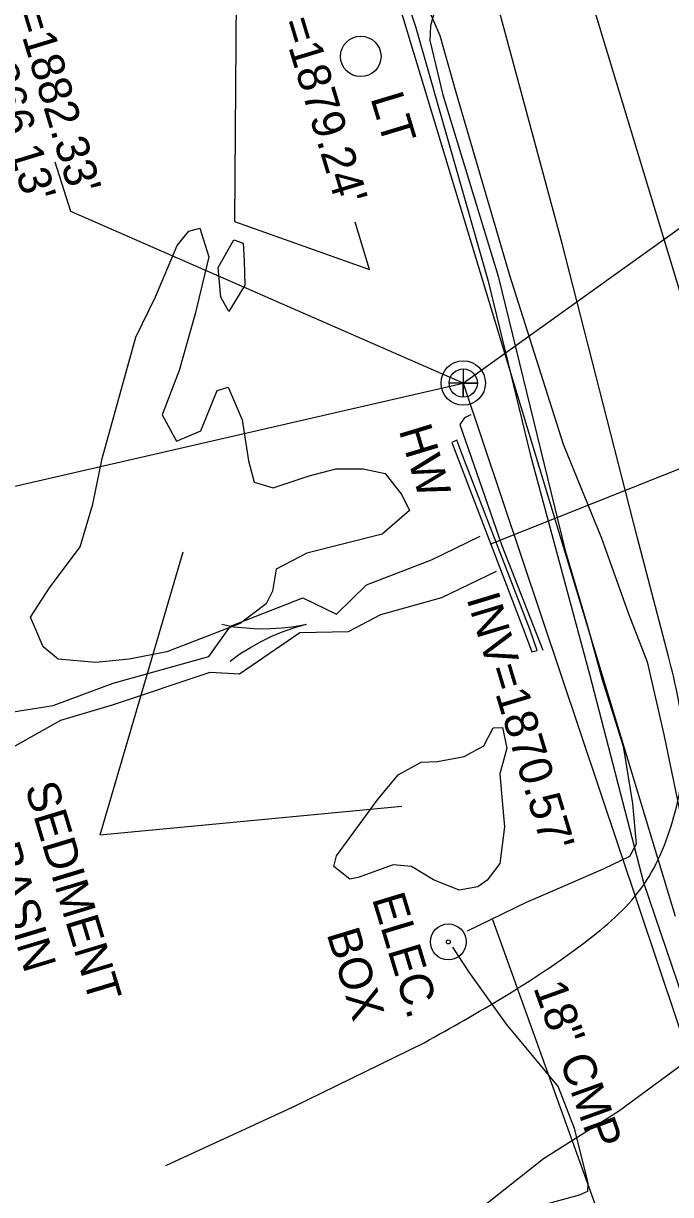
# Model space of a CAD drawing. Extents: x 553786 to 558838, y 502329 to 507342.
# Drawn here: x 555425.2 to 555503.7, y 503924.4 to 504066.5 of the extents above; entities that cross this region are included whole.
import ezdxf

# ---------------------------------------------------------------- set-up
doc = ezdxf.new("R2010")
doc.units = 0
for name, color, linetype in [('Exist Hydro Jurisdictional Stream or Body of Water', 7, 'Continuous'), ('Exist Hydro Stream Flow Arrow CELL', 7, 'Continuous'), ('Exist Hydrographic Top of Bank', 7, 'Continuous'), ('Exist Other Culture Area Outline Leader', 7, 'Continuous'), ('Exist Other Culture Area Outline Text', 7, 'Continuous'), ('Exist Structure Minor Head and End Wall Text', 7, 'Continuous'), ('Exist Structure Minor Pipes CMAP 103inx71in Invert', 7, 'Continuous'), ('Exist Structure Minor Pipes CMP 18 Inch', 7, 'Continuous'), ('Exist Structure Minor Pipes CMP 18 Inch Text', 7, 'Continuous'), ('Exist Structure Minor Pipes CMP 30 Inch', 7, 'Continuous'), ('Exist Structure Minor Pipes CMP 30 Inch Invert', 7, 'Continuous'), ('Exist Structure Minor Pipes CMP 30 Inch Leader', 7, 'Continuous'), ('Exist Utilities Other Located Object CELL', 7, 'Continuous'), ('Exist Utilities Other Located Object Text', 7, 'Continuous'), ('Exist Utilities Other Pole CELL', 7, 'Continuous'), ('Exist Utilities Other Pole Text', 7, 'Continuous'), ('Exist Utilities Sanitary Sewer Manhole Leader', 7, 'Continuous'), ('Exist Utilities Sanitary Sewer Manhole Text', 7, 'Continuous'), ('Exist Utilities Sanitary Sewer UG Line', 7, 'Continuous'), ('Exist Utilities Sanitary Sewer UG Line Invert Elevation', 7, 'Continuous'), ('Exist Vertical Profile Ground Line', 7, 'Continuous'), ('Prop Drainage Structure Catch Basin Grate 840 03F Label', 7, 'Continuous'), ('Prop Drainage Structure Pipe Alternate 24in', 7, 'Continuous'), ('Prop Drainage Structure Pipe Alternate 36in', 7, 'Continuous'), ('Prop Drainage Structure Pipe RCP 15in Class III', 7, 'Continuous'), ('Prop Drainage Structure Pipe RCP 15in Class III Label', 7, 'Continuous'), ('Prop Drainage Structure Pipe RCP 18in Class IV', 7, 'Continuous'), ('Prop Earthen Structure Tail Ditch Label', 7, 'Continuous'), ('Prop Erosion Rip Rap Pad Outlet for Jurisdictional Stream CELL', 7, 'Continuous'), ('Sheet Layout Plan Border', 7, 'Continuous')]:
    doc.layers.add(name, color=color, linetype=linetype)

# ---------------------------------------------------------------- blocks, each defined once
blk = doc.blocks.new('EXIST UTILITIES SANITARY SEWER MANHOLE')
at = {"layer": 'Prop Drainage Structure Catch Basin Grate 840 03F Label'}
blk.add_lwpolyline([(0, 0.03425), (0, -0.03425), (0, 0), (0.03425, 0), (-0.03425, 0)], dxfattribs=at)
for radius in [0.05389, 0.03425]:
    blk.add_circle((0, 0), radius, dxfattribs=at)

msp = doc.modelspace()

# ---------------------------------------------------------------- linework, layer by layer
at = {"layer": 'Exist Hydro Jurisdictional Stream or Body of Water'}
for points in [[(555450.1, 504031.56), (555449.11, 504033.28), (555448.78, 504036.89), (555450.72, 504040.25), (555451.83, 504039.85), (555451.96, 504037.68), (555452.02, 504034.76), (555450.1, 504031.56)], [(555410.59, 503980.79), (555422.92, 503982.82), (555428.76, 503983.74), (555436.04, 503986.44), (555447.65, 503989.69), (555450.28, 503993.37), (555459.09, 503996.81), (555463.15, 503994.84), (555466.8, 503998.39), (555474.67, 504001.41), (555480.6, 504004.27)], [(555411.01, 503976.66), (555422.87, 503978.1), (555429.7, 503981.94), (555435.97, 503983.8), (555447.83, 503987.78), (555451.37, 503987.58), (555458.73, 503992.59), (555464.6, 503992.73), (555468.52, 503994.78), (555475.95, 503996.86), (555482.57, 504000.03)]]:
    msp.add_lwpolyline(points, dxfattribs=at)
at = {"layer": 'Exist Hydro Stream Flow Arrow CELL'}
msp.add_line((555454.64, 503992.47), (555454.64, 503992.47), dxfattribs=at)
for points in [[(555449.25, 503993.59), (555450.69, 503993.3), (555452.18, 503993.17), (555453.66, 503993.06), (555455.1, 503993.07), (555456.58, 503993.16), (555458.07, 503993.34), (555459.51, 503993.59)], [(555450.27, 503989.13), (555451.44, 503990.01), (555452.73, 503990.78), (555454.01, 503991.52), (555455.32, 503992.14), (555456.69, 503992.7), (555458.1, 503993.19), (555459.51, 503993.59)]]:
    msp.add_lwpolyline(points, dxfattribs=at)
at = {"layer": 'Exist Hydrographic Top of Bank'}
msp.add_lwpolyline([(555454.73, 503900.13), (555461.06, 503904.46), (555466.29, 503907.66), (555471.13, 503910.31), (555473.27, 503914.4), (555479.75, 503922.01), (555488.3, 503928.78), (555497.38, 503934.53), (555512.87, 503945.92), (555521.69, 503954.59), (555530.33, 503963.4), (555533.78, 503966.67), (555538.03, 503970.02), (555540.47, 503971.18), (555541.14, 503972.36), (555541.05, 503973.88), (555540.1, 503976.62), (555537.96, 503985.99), (555539.43, 503986.04), (555541.64, 503987.48), (555544.42, 503988.72)], dxfattribs=at)
at = {"layer": 'Exist Other Culture Area Outline Leader'}
for p in [(555444.5, 504002.35), (555471.09, 503971.47)]:
    msp.add_line(p, (555434.42, 503967.99), dxfattribs=at)
at = {"layer": 'Exist Structure Minor Pipes CMP 18 Inch'}
msp.add_line((555496.09, 503918.99), (555482.14, 503957.75), dxfattribs=at)
at = {"layer": 'Exist Structure Minor Pipes CMP 30 Inch'}
msp.add_line((555451.41, 504141.86), (555450.8, 504042.46), dxfattribs=at)
at = {"layer": 'Exist Structure Minor Pipes CMP 30 Inch Leader'}
msp.add_lwpolyline([(555450.8, 504042.46), (555467.18, 504036.63), (555465.44, 504042.37)], dxfattribs=at)
at = {"layer": 'Exist Utilities Other Located Object CELL'}
for radius in [2.18, 0.24]:
    msp.add_circle((555476.73, 503955.05), radius, dxfattribs=at)
at = {"layer": 'Exist Utilities Other Pole CELL'}
msp.add_circle((555466.1, 504062.51), 2.46, dxfattribs=at)
at = {"layer": 'Exist Utilities Sanitary Sewer Manhole Leader'}
msp.add_lwpolyline([(555478.54, 504022.87), (555430.93, 504043.7), (555429.02, 504049.68)], dxfattribs=at)
at = {"layer": 'Exist Utilities Sanitary Sewer UG Line'}
for p, q in [((555478.54, 504022.87), (555548.76, 504073.12)), ((555139.99, 503944.95), (555478.54, 504022.87)), ((555478.54, 504022.87), (555570.8, 503747.32))]:
    msp.add_line(p, q, dxfattribs=at)
at = {"layer": 'Exist Vertical Profile Ground Line'}
for points in [[(555433.43, 504150.93), (555435.21, 504143.77), (555439.28, 504132.06), (555443.72, 504117.58), (555448.57, 504102.98), (555451.64, 504099.28), (555458.9, 504092.28), (555463.53, 504086.55), (555466.67, 504083.23), (555473.34, 504070.52), (555475.68, 504065.03), (555477.64, 504058.17), (555484.14, 504035.95), (555490.65, 504015.45), (555495.3, 504004.06), (555498.56, 503994.99), (555500.88, 503989.04), (555502.87, 503980.23), (555504.78, 503971.04), (555509.33, 503958.36), (555513.88, 503945.7), (555518.65, 503930.05), (555518.54, 503922.95)], [(555475.23, 504068.51), (555474.56, 504066.21), (555474.48, 504064.44), (555476.06, 504057.84), (555482.79, 504035.83), (555487.95, 504014.64), (555490.91, 504002.55), (555493.6, 503993.51), (555495.34, 503987.02), (555497.95, 503978.82), (555499.07, 503971.84), (555499.52, 503966.9), (555498.7, 503965.42), (555495.6, 503963.92), (555490.59, 503961.74), (555486.19, 503959.84), (555479.03, 503956.36)], [(555477.25, 503954.4), (555479.22, 503951.36), (555483.75, 503945.05), (555490.05, 503937.45), (555492.02, 503932.45), (555493.66, 503925.77), (555493.64, 503924.77), (555492.62, 503924.3), (555484.18, 503922.02), (555478.39, 503918.47), (555469.06, 503912.69), (555453.02, 503904.48)]]:
    msp.add_lwpolyline(points, dxfattribs=at)
at = {"layer": 'Prop Drainage Structure Pipe Alternate 24in'}
msp.add_lwpolyline([(555425.86, 504224.7), (555428.87, 504213.11), (555437.48, 504180.87), (555443.86, 504161.62), (555449.94, 504139.06), (555455.37, 504118.93), (555462.09, 504098.48), (555472.75, 504066.14), (555481.58, 504035.23), (555486.66, 504014.25), (555493.86, 503987.55), (555500.4, 503962.25), (555506.61, 503944.04), (555513.8, 503922.45), (555526.9, 503890.29), (555537.86, 503859.06), (555549.89, 503821.22), (555549.16, 503799.4), (555550.9, 503782.96), (555554.95, 503765.26), (555558.46, 503752.22), (555561.63, 503739.32), (555563.86, 503731.68)], dxfattribs=at)
at = {"layer": 'Prop Drainage Structure Pipe Alternate 36in'}
for points in [[(555503.47, 503989.67), (555499.64, 504004.22), (555490.53, 504039.82), (555480.15, 504078.29), (555469.77, 504113.9), (555458.62, 504151.44), (555447.67, 504188.15), (555436.59, 504224.22)], [(555442.44, 503927.91), (555457.8, 503934.99), (555473.8, 503942.81)]]:
    msp.add_lwpolyline(points, dxfattribs=at)
msp.add_spline([(555473.8, 503942.81), (555483.53, 503948.42), (555493.32, 503955.02), (555500.1, 503961.5), (555504.11, 503970.27), (555505.27, 503979.46), (555503.47, 503989.67)], degree=3, dxfattribs=at)
at = {"layer": 'Prop Drainage Structure Pipe RCP 15in Class III'}
msp.add_line((555481.88, 504003.36), (555528.79, 504022.07), dxfattribs=at)
at = {"layer": 'Prop Drainage Structure Pipe RCP 15in Class III Label'}
msp.add_line((555424.8, 504220.5), (555504.25, 503958.16), dxfattribs=at)
at = {"layer": 'Prop Drainage Structure Pipe RCP 18in Class IV'}
msp.add_lwpolyline([(555478.08, 504013.23), (555485.97, 503992.64), (555486.86, 503990.24), (555487.53, 503990.43), (555486.67, 503992.9), (555478.7, 504013.48), (555477.77, 504015.92), (555477.17, 504015.65), (555478.08, 504013.23)], dxfattribs=at)
at = {"layer": 'Prop Earthen Structure Tail Ditch Label'}
for points in [[(555442.58, 503990.25), (555438.01, 503989.37), (555433.96, 503988.95), (555429.4, 503989.35), (555427.58, 503990.87), (555426.02, 503994.44), (555428.35, 503998.01), (555432.04, 504003), (555433.57, 504008.15), (555434.74, 504013.71), (555438.82, 504028.45), (555441.21, 504033.34), (555443.83, 504039.55), (555445.25, 504041.3), (555446.58, 504041.65), (555447.68, 504038.18), (555446.01, 504031.28), (555444.08, 504024.39), (555442, 504018.99), (555443.74, 504015.8), (555446.7, 504017.07), (555448.66, 504021.96), (555450.01, 504022.38), (555451.7, 504018.42), (555452.48, 504013.44), (555453.15, 504010.82), (555455.48, 504010.15), (555459.83, 504011.6), (555463.07, 504012.47), (555466.39, 504012.46), (555469.08, 504011.9), (555471.1, 504009.3), (555472, 504007.42), (555468.71, 504004.54), (555459.54, 504002.23), (555455.82, 504000.29), (555455.38, 503997.6), (555454.62, 503996.07), (555451.46, 503993.68), (555442.58, 503990.25)], [(555463.15, 503965.5), (555468.13, 503972.28), (555470.63, 503975.33), (555473.44, 503976.88), (555475.4, 503976.96), (555478.67, 503977.56), (555481.05, 503978.84), (555482.16, 503981.01), (555483.3, 503981.08), (555483.83, 503978.57), (555482.99, 503975.45), (555483.23, 503972.6), (555483.54, 503969.03), (555482.97, 503964.58), (555481.43, 503962.53), (555480.32, 503961.73), (555478.03, 503961.33), (555474.95, 503962.57), (555472.27, 503964.22), (555470.04, 503964.39), (555465.79, 503962.86), (555464.78, 503962.66), (555462.83, 503964.21), (555463.15, 503965.5)]]:
    msp.add_lwpolyline(points, dxfattribs=at)
at = {"layer": 'Prop Erosion Rip Rap Pad Outlet for Jurisdictional Stream CELL'}
msp.add_lwpolyline([(555479.46, 504019.01), (555478.7, 504018.66), (555478.11, 504017.82), (555483.24, 504003.17), (555488.18, 503990.45)], dxfattribs=at)
at = {"layer": 'Sheet Layout Plan Border'}
msp.add_line((555446.33, 504227.02), (555525.79, 503964.68), dxfattribs=at)

# ---------------------------------------------------------------- block references
at = {"layer": 'Prop Drainage Structure Catch Basin Grate 840 03F Label', "xscale": 50, "yscale": 50}
msp.add_blockref('EXIST UTILITIES SANITARY SEWER MANHOLE', (555478.54, 504022.87), dxfattribs=at)

# ---------------------------------------------------------------- texts
at = {"layer": 'Exist Other Culture Area Outline Text'}
for s, p in [('SEDIMENT', (555425.31, 503973.83)), ('BASIN', (555420.75, 503966.46))]:
    msp.add_text(s, height=4, rotation=286.85, dxfattribs=at).set_placement(p)
at = {"layer": 'Exist Structure Minor Head and End Wall Text'}
msp.add_text('HW', height=4, rotation=286.85, dxfattribs=at).set_placement((555470.69, 504017.15))
at = {"layer": 'Exist Structure Minor Pipes CMAP 103inx71in Invert'}
msp.add_text("INV=1870.57'", height=4, rotation=286.85, dxfattribs=at).set_placement((555478.92, 503996.74))
at = {"layer": 'Exist Structure Minor Pipes CMP 18 Inch Text'}
msp.add_text('18" CMP', height=4, rotation=289.803, dxfattribs=at).set_placement((555487.01, 503949.51))
at = {"layer": 'Exist Structure Minor Pipes CMP 30 Inch Invert'}
msp.add_text("INV=1879.24'", height=4, rotation=286.85, dxfattribs=at).set_placement((555453.8, 504075.19))
at = {"layer": 'Exist Utilities Other Located Object Text'}
for s, p in [('ELEC. ', (555467.44, 503960.31)), ('BOX', (555461.94, 503956.05))]:
    msp.add_text(s, height=4, rotation=286.85, dxfattribs=at).set_placement(p)
at = {"layer": 'Exist Utilities Other Pole Text'}
msp.add_text('LT', height=4, rotation=286.85, dxfattribs=at).set_placement((555467.25, 504057.46))
at = {"layer": 'Exist Utilities Sanitary Sewer Manhole Text'}
msp.add_text("TOP=1882.33'", height=4, rotation=286.85, dxfattribs=at).set_placement((555420.88, 504078.44))
at = {"layer": 'Exist Utilities Sanitary Sewer UG Line Invert Elevation'}
msp.add_text("INV=1866.13'", height=4, rotation=286.85, dxfattribs=at).set_placement((555416, 504075.51))

doc.saveas('drawing.dxf')
